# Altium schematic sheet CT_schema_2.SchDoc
size 240 x 321 mm
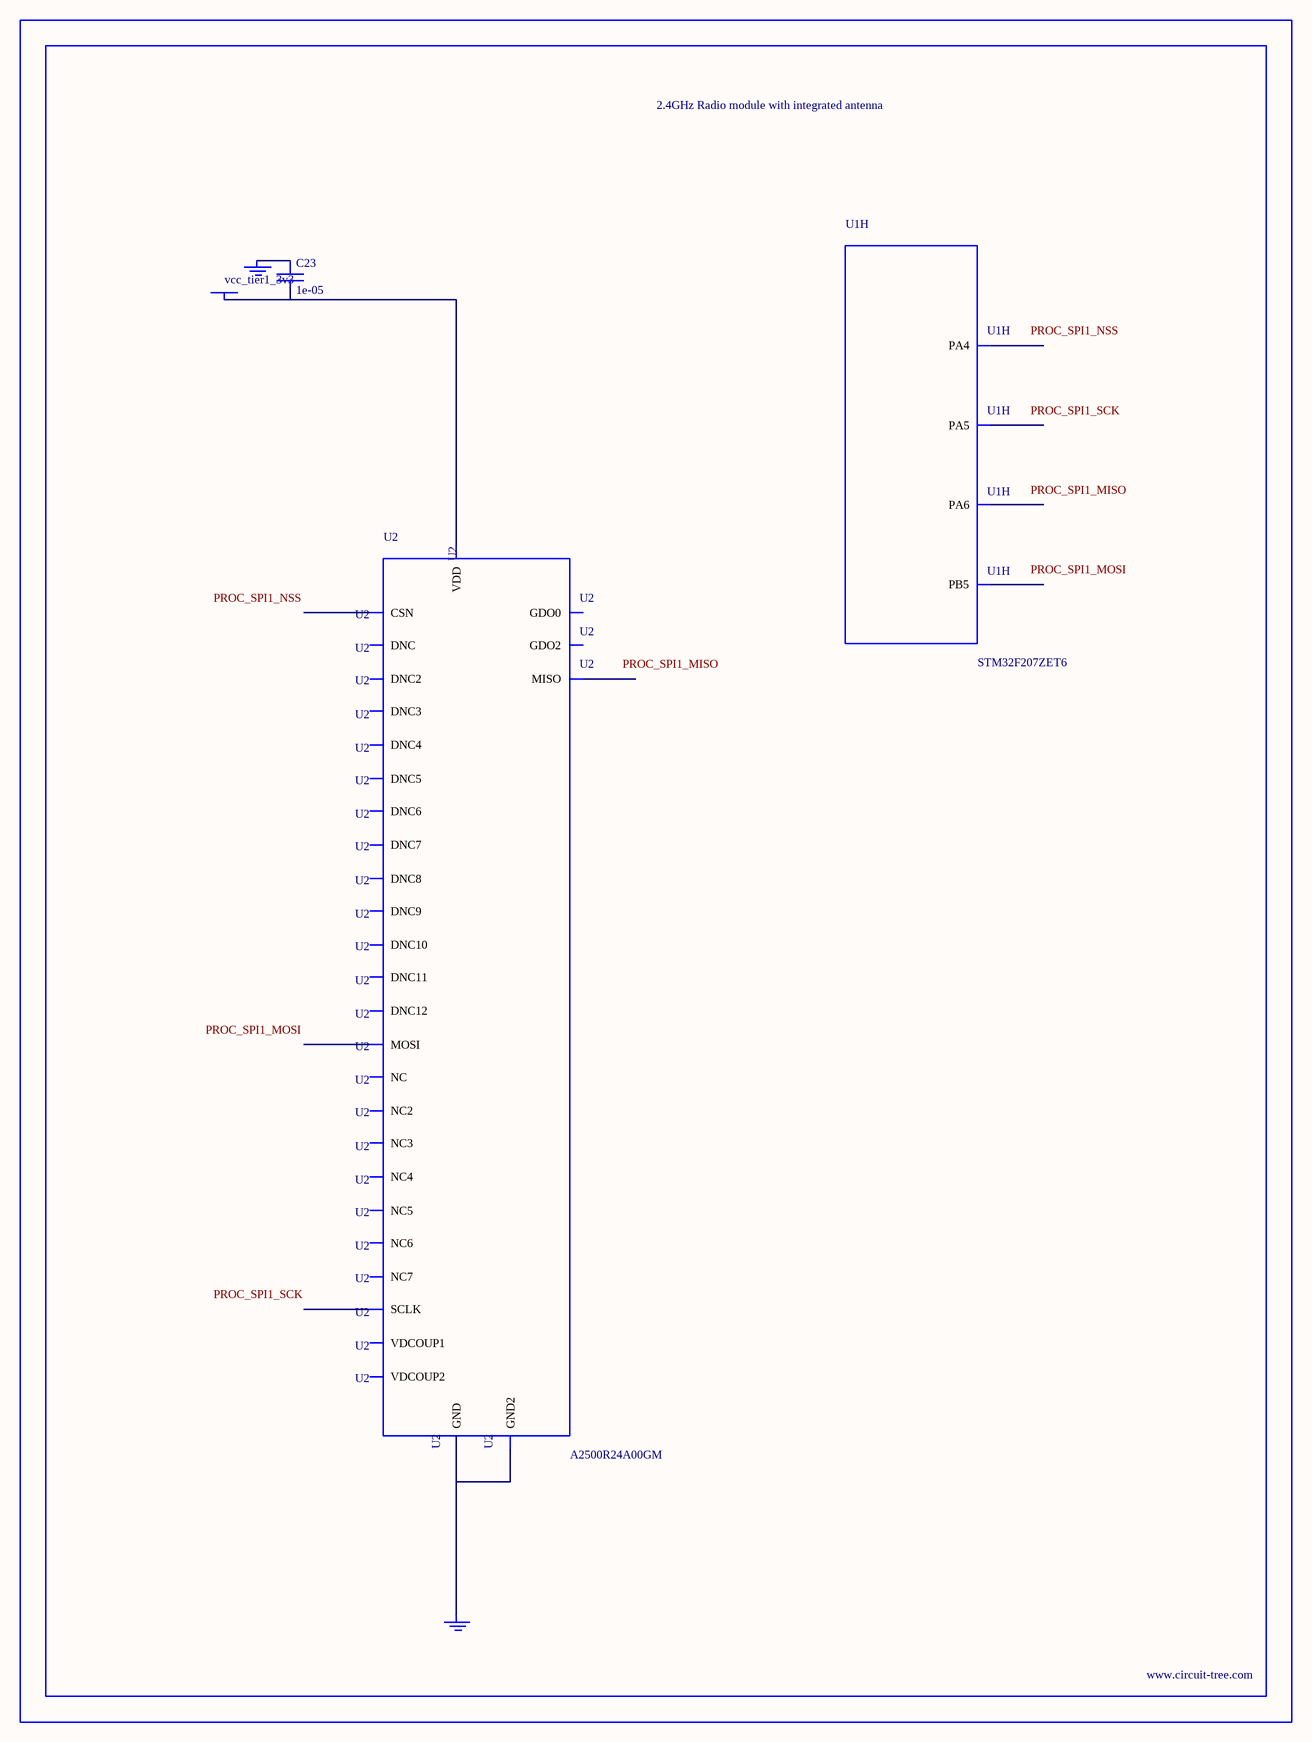
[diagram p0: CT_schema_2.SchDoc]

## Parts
BORDER1  (no value)
C23  1e-05  [C0805]
GND_INSTANCE_1_0  (no value)
GND_INSTANCE_1_1  (no value)
POWER_INSTANCE_1_0  vcc_tier1_3v3
U1  STM32F207ZET6  [LQFP144]  (part H of 13)
U2  A2500R24A00GM  [A2500R24A00GM]

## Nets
NetC23_1: C23.1 GND_INSTANCE_1_0.0(GND)
NetC23_2: C23.2 POWER_INSTANCE_1_0.0(PWR) U2.18(VDD)
NetGND_INSTANCE_1_1_0: GND_INSTANCE_1_1.0(GND) U2.8(GND) U2.17(GND2)

Not connected (* = marked no-connect by the designer): U1 40(PA4) 41(PA5) 42(PA6) 135(PB5); U2 1(DNC) 2(DNC2) 3(DNC3) 4(NC) 5(NC2) 6(NC3) 7(VDCOUP1) 9(SCLK) 10(MISO) 11(MOSI) 12(CSN) 13(GDO0) 14(GDO2) 15(VDCOUP2) 16(NC4) 19(NC5) 20(NC6) 21(NC7) 22(DNC4) 23(DNC5) 24(DNC6) 25(DNC7) 26(DNC8) 27(DNC9) 28(DNC10) 29(DNC11) 30(DNC12)

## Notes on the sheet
- Labels drawn without touching a wire or pin: PROC_SPI1_MISO, PROC_SPI1_MOSI, PROC_SPI1_NSS, PROC_SPI1_SCK

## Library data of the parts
BORDER1 = BORDER_PAGE1
C23 = C0805C106K8RACTU
GND_INSTANCE_1_0 GND_INSTANCE_1_1 = GND
POWER_INSTANCE_1_0 = PWR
